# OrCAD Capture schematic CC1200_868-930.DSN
size A3; rev: A; note: CC120XEM_868_915
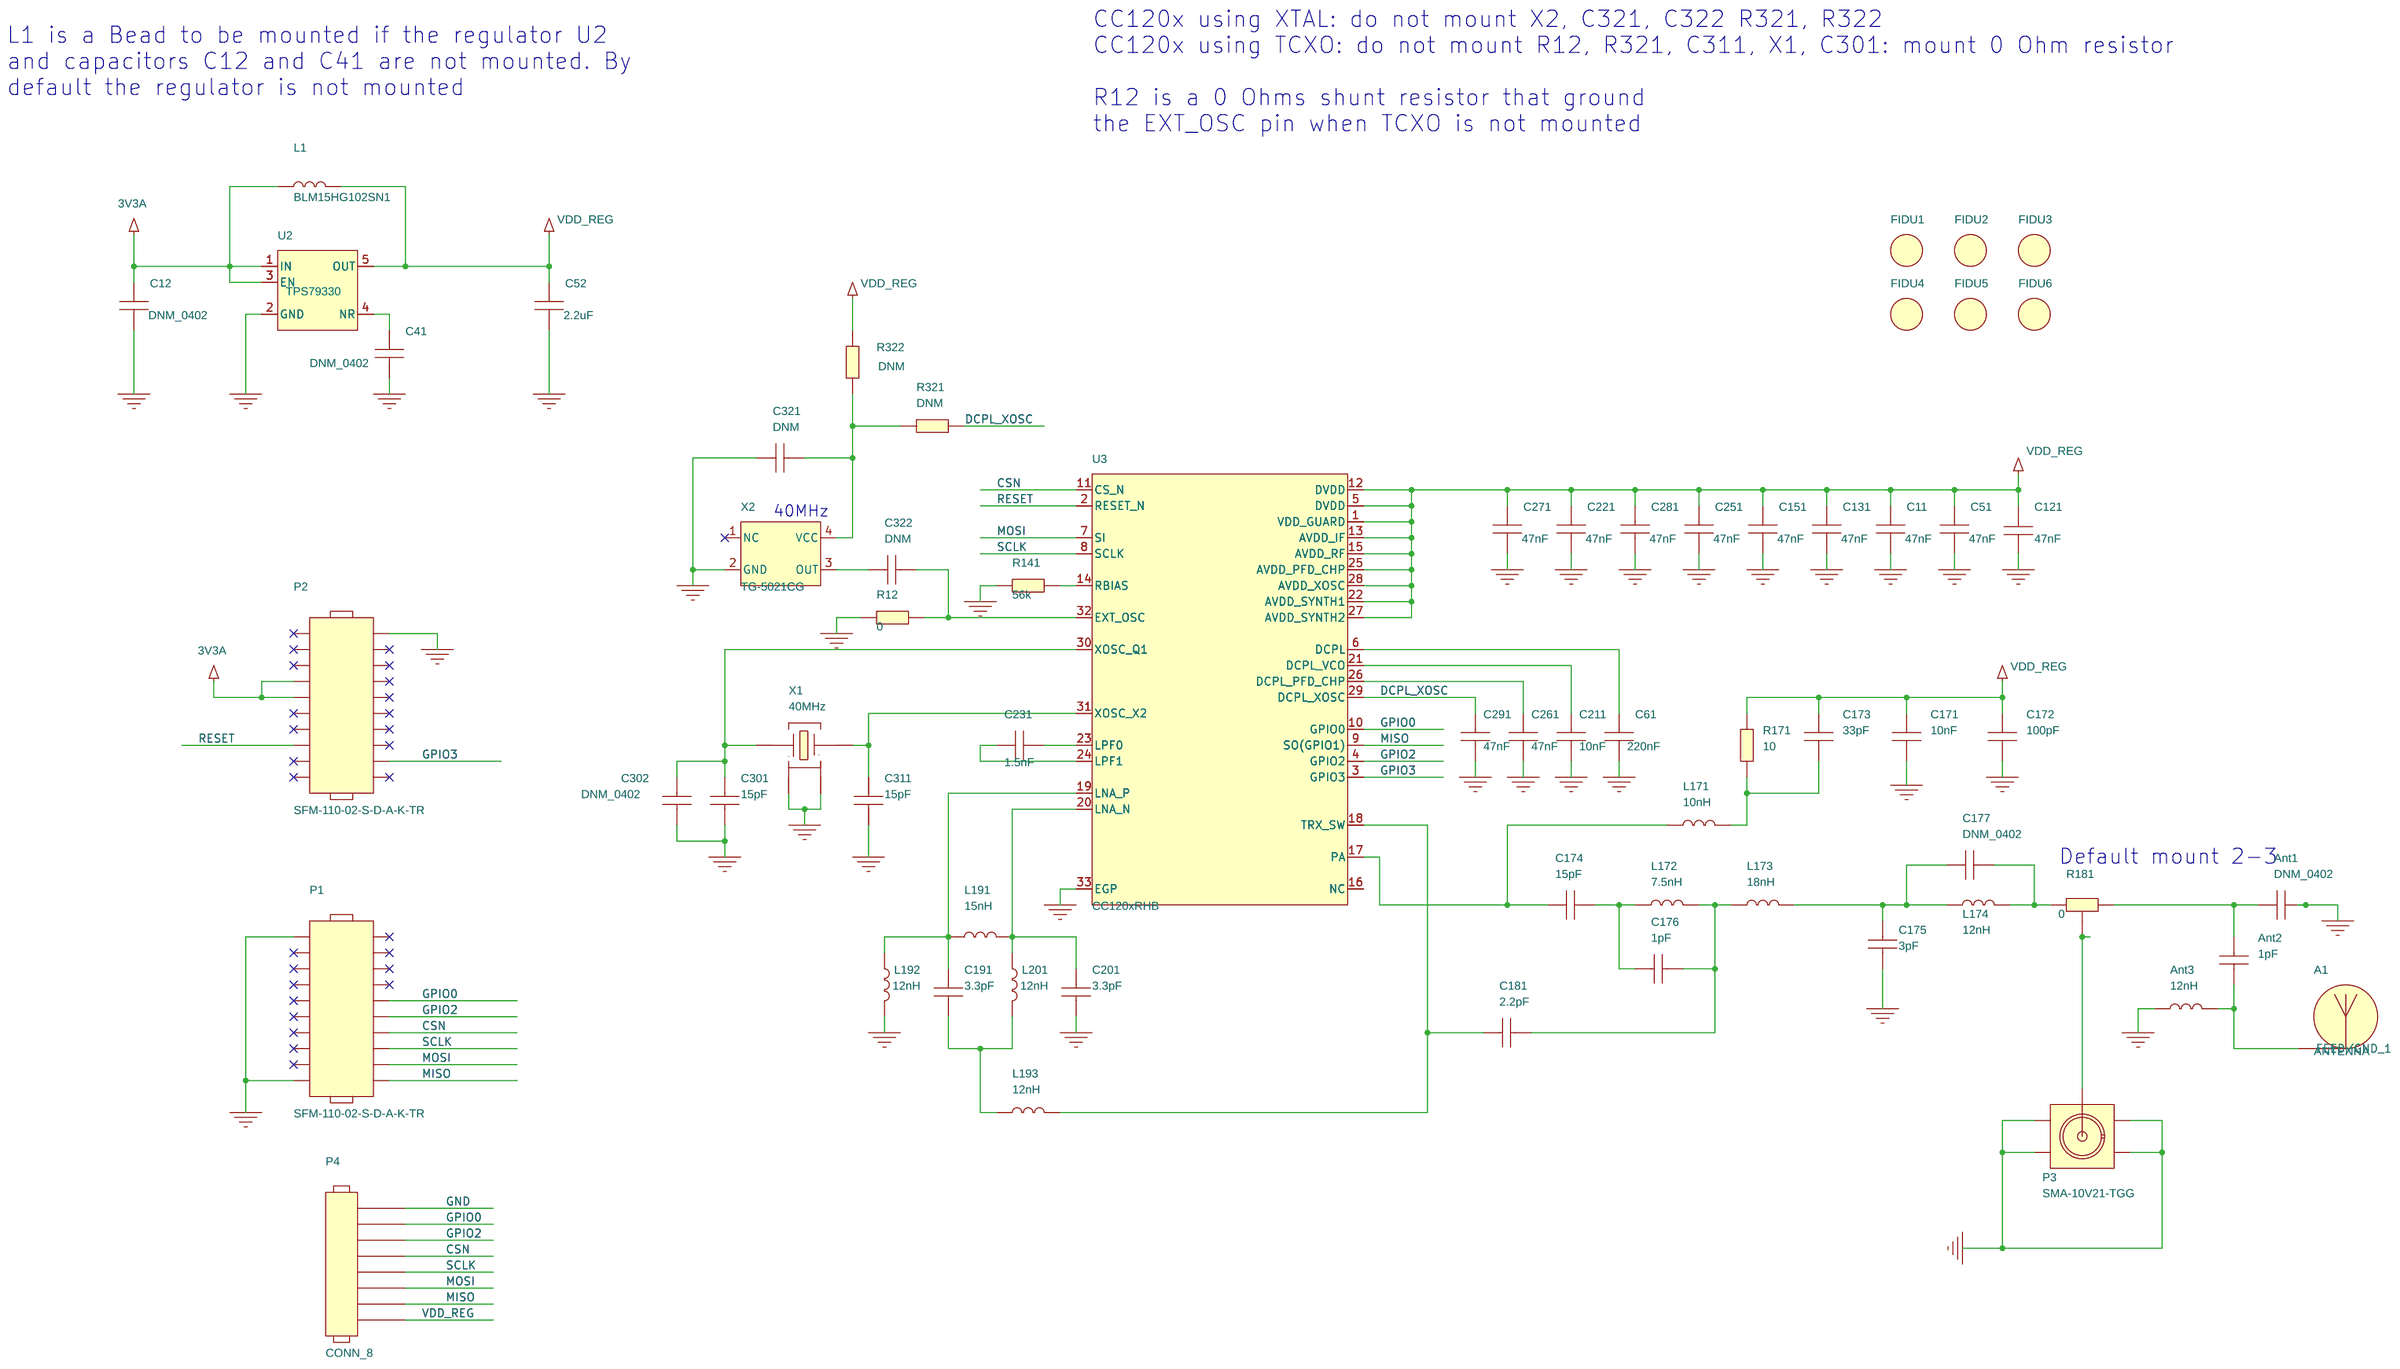
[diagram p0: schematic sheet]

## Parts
A1  ANTENNA  [Antenna868_915MHz]
Ant1  DNM_0402  [CAPC1005X60N]
Ant2  1pF  [CAPC1005X60N]
Ant3  12nH  [IND_0402CSAN]
C11  47nF  [CAPC1005X60N]
C12  DNM_0402  [CAPC1005X60N]
C41  DNM_0402  [CAPC1005X60N]
C51  47nF  [CAPC1005X60N]
C52  2.2uF  [CAPC1608X90N]
C61  220nF  [CAPC1005X60N]
C121  47nF  [CAPC1005X60N]
C131  47nF  [CAPC1005X60N]
C151  47nF  [CAPC1005X60N]
C171  10nF  [CAPC1005X60N]
C172  100pF  [CAPC1005X60N]
C173  33pF  [CAPC1005X60N]
C174  15pF  [CAPC1005X60N]
C175  3pF  [CAPC1005X60N]
C176  1pF  [CAPC1005X60N]
C177  DNM_0402  [CAPC1005X60N]
C181  2.2pF  [CAPC1005X60N]
C191  3.3pF  [CAPC1005X60N]
C201  3.3pF  [CAPC1005X60N]
C211  10nF  [CAPC1005X60N]
C221  47nF  [CAPC1005X60N]
C231  1.5nF  [CAPC1005X60N]
C251  47nF  [CAPC1005X60N]
C261  47nF  [CAPC1005X60N]
C271  47nF  [CAPC1005X60N]
C281  47nF  [CAPC1005X60N]
C291  47nF  [CAPC1005X60N]
C301  15pF  [CAPC1005X60N]
C302  DNM_0402  [CAPC1005X60N]
C311  15pF  [CAPC1005X60N]
C321  DNM  [CAPC1005X60N]
C322  DNM  [CAPC1005X60N]
FIDU1  FIDU_1.27mm  [FID127X142]
FIDU2  FIDU_1.27mm  [FID127X142]
FIDU3  FIDU_1.27mm  [FID127X142]
FIDU4  FIDU_1.27mm  [FID127X142]
FIDU5  FIDU_1.27mm  [FID127X142]
FIDU6  FIDU_1.27mm  [FID127X142]
L1  BLM15HG102SN1  [INDC1005X60N]
L171  10nH  [IND_0402CSAN]
L172  7.5nH  [IND_0402CSAN]
L173  18nH  [INDC1005X60N]
L174  12nH  [IND_0402CSAN]
L191  15nH  [IND_0402CSAN]
L192  12nH  [IND_0402CSAN]
L193  12nH  [IND_0402CSAN]
L201  12nH  [IND_0402CSAN]
P1  SFM-110-02-S-D-A-K-TR  [SAMTEC_SFM11002AN]
P2  SFM-110-02-S-D-A-K-TR  [SAMTEC_SFM11002AN]
P3  SMA-10V21-TGG  [HUSTSAN_SMA10V21TGGAN]
P4  CONN_8  [CON_1x8PAD_t1900cir1100]
R12  0  [RESC1005X40N]
R141  56k  [RESC1005X40N]
R171  10  [RESC1005X40N]
R181  0  [RESC1005X40AN]
R321  DNM  [RESC1005X40N]
R322  DNM  [RESC1005X40N]
U2  TPS79330  [SOT95P280X145-5N]
U3  CC120xRHB  [QFNFC50P500X500X100-33BN]
X1  40MHz  [OSCCC250X320X80-4N]
X2  TG-5021CG  [OSCCC200X250X90-4BN]

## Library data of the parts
A1 = ANTENNA: MECHANIC, ANTENNA PCB HELIX 868/915MHz, SMD; AutoDoc File: http://notefied-dynamic-precision.com/DB/Apps/Desktop/Item/Object.aspx?id=87165; Frequency: 868/915MHz; MPN: Antenna PCB helix 868/915MHz; MPN Status: ACTIVE; Manufacturer: TEXAS INSTRUMENTS; Max Oper Temp: N/A; Min Oper Temp: N/A; Mounting Type: SMD; NOTE Status: PREFERRED; Part Number: 13-00397; Part Type: MECHANIC\ANTENNA; Revision: R001; RoHS Status: ROHS_COMPLIANT
Ant1 C177 = CAPACITOR: CAPACITOR, CERAMIC, N/A VALUE, -55DEGC/+125DEGC, 0402, SMD; ALT_SYMBOLS: CAPC1005X60L,CAPC1005X60M; AutoDoc File: http://notefied-dynamic-precision.com/DB/Apps/Desktop/Item/Object.aspx?id=84862; Budget Currency: USD; Budget Price: 0.00589; MPN: CAPACITOR_0402_DNM_N/A_M; MPN Status: ACTIVE; Manufacturer: Manufacturer selection; Max Oper Temp: +125DEGC; Min Oper Temp: -55DEGC; Mounting Type: SMD; NOTE Status: PREFERRED; PCB Package: 0402; Packing Size: 10000; Packing Type: TAPE_&_REEL; Part Number: 02-04164; Part Type: CAPACITOR\CERAMIC\0402; Revision: R000; RoHS Status: PART NOT KNOWN
Ant2 C176 = CAPACITOR: CAPACITOR, CERAMIC C0G/NP0, 1pF, 50V, -0.1pF/+0.1pF, -55DEGC/+125DEGC, 0402, SMD; ALT_SYMBOLS: CAPC1005X60L,CAPC1005X60M; AutoDoc File: http://notefied-dynamic-precision.com/DB/Apps/Desktop/Item/Object.aspx?id=86074; Budget Currency: USD; Budget Price: 0.008; Datasheet URL 1: http://search.murata.co.jp/Ceramy/image/img/PDF/ENG/GRM1555C1H1R0BA01.pdf; Datasheet URL 2: http://search.murata.co.jp/Ceramy/image/img/PDF/ENG/GRM1555C1H1R0BA01.pdf; Dielectric Type: C0G/NP0; MPN: GRM1555C1H1R0BA01D; MPN Status: ACTIVE; Manufacturer: MURATA; Max Oper Temp: +125DEGC; Max TC: +30PPM/DEGC; Max Tol: +0.1pF; Min Oper Temp: -55DEGC; Min TC: -30PPM/DEGC; Min Tol: -0.1pF; Mounting Type: SMD; NOTE Status: PREFERRED; PCB Package: 0402; Packing Size: 10000; Packing Type: TAPE_&_REEL; Part Number: 02-04367; Part Type: CAPACITOR\CERAMIC\0402; Revision: R001; RoHS Status: ROHS_COMPLIANT; Rtd Voltage: 50V
Ant3 L174 L192 L193 L201 = INDUCTOR: INDUCTOR, CHIP, 12nH, -5%/+5%, 0.5A, -55DEGC/+125DEGC, 0402, SMD; ALT_SYMBOLS: IND_0402CSAM,IND_0402CSAL; AutoDoc File: http://notefied-dynamic-precision.com/DB/Apps/Desktop/Item/Object.aspx?id=86088; Budget Currency: USD; Budget Price: 0.143; Datasheet URL 1: http://search.murata.co.jp/Ceramy/image/img/PDF/ENG/L0075S0080LQW15A_00.pdf; Datasheet URL 2: http://search.murata.co.jp/Ceramy/image/img/PDF/ENG/L0075S0080LQW15A_00.pdf; Frequency: 5.5GHz; MPN: LQW15AN12NJ00D; MPN Status: ACTIVE; Manufacturer: MURATA; Max Oper Temp: +125DEGC; Max Tol: +5%; Min Oper Temp: -55DEGC; Min Tol: -5%; Mounting Type: SMD; NOTE Status: PREFERRED; PCB Package: 0402; Packing Size: 10000; Packing Type: TAPE_&_REEL; Part Number: 03-06556; Part Type: INDUCTOR\CHIP\0402; Resistance: 0.14; Revision: R001; RoHS Status: ROHS_COMPLIANT; Rtd Current: 0.5A; WEIGHT: 0.0008g
C11 C51 C121 C131 C151 C221 C251 C261 C271 C281 C291 = CAPACITOR: CAPACITOR, CERAMIC, X7R, 47nF, 25V, -10%/+10%, -55DEGC/+125DEGC, 0402, SMD; ALT_SYMBOLS: CAPC1005X60L,CAPC1005X60M; AutoDoc File: https://notefied-dynamic-precision.com/NotefiedWebServices/AutoDocs.aspx?itemid=85866; Datasheet URL 1: http://search.murata.co.jp/Ceramy/image/img/PDF/ENG/GRM155R71E473KA88.pdf; Datasheet URL 2: http://search.murata.co.jp/Ceramy/image/img/PDF/ENG/GRM155R71E473KA88.pdf; Dielectric Type: X7R; LifeCycle Status: ACTIVE; MPN: GRM155R71E473KA88D; MPN Status: ACTIVE; Manufacturer: MURATA; Max Oper Temp: +125DEGC; Max Tol: +10%; Min Oper Temp: -55DEGC; Min Tol: -10%; Mounting Type: SMD; NOTE Status: PREFERRED; PCB Package: 0402; Packing Size: 10000; Packing Type: TAPE_&_REEL; Part Number: 02-04324; Part Type: CAPACITOR\CERAMIC\0402; Revision: R001; RoHS Status: ROHS_COMPLIANT; Rtd Voltage: 25V
C12 C41 C302 = CAPACITOR: CAPACITOR, CERAMIC, N/A VALUE, -55DEGC/+125DEGC, 0402, SMD; ALT_SYMBOLS: CAPC1005X60L,CAPC1005X60M; AutoDoc File: https://notefied-dynamic-precision.com/NotefiedWebServices/AutoDocs.aspx?itemid=84862; Budget Currency: USD; Budget Price: 0.00589; MPN: CAPACITOR_0402_DNM_N/A_M; MPN Status: ACTIVE; Manufacturer: Manufacturer selection; Max Oper Temp: +125DEGC; Min Oper Temp: -55DEGC; Mounting Type: SMD; NOTE Status: PREFERRED; PCB Package: 0402; Packing Size: 10000; Packing Type: TAPE_&_REEL; Part Number: 02-04164; Part Type: CAPACITOR\CERAMIC\0402; Revision: R000; RoHS Status: PART NOT KNOWN
C52 = CAPACITOR: CAPACITOR, CERAMIC X5R, 2.2uF, 10V, -10%/+10%, -55DEGC/+85DEGC, 0603, SMD; ALT_SYMBOLS: CAPC1608X90L,CAPC1608X90M; AutoDoc File: https://notefied-dynamic-precision.com/NotefiedWebServices/AutoDocs.aspx?itemid=74514; Budget Currency: EUR; Budget Price: 0.124; Datasheet URL 1: http://search.murata.co.jp/Ceramy/CatalogAction.do?sHinnm=GRM39X5R225K10&sNHinnm=GRM188R61A225KE34&sNhin_key=GRM188R61A225KE34D&sLang=en&sParam=GRM188R61A225KE34D; Datasheet URL 2: http://search.murata.co.jp/Ceramy/CatalogAction.do?sHinnm=GRM39X5R225K10&sNHinnm=GRM188R61A225KE34&sNhin_key=GRM188R61A225KE34D&sLang=en&sParam=GRM188R61A225KE34D; Dielectric Type: X5R; MPN: GRM188R61A225KE34D; MPN Status: ACTIVE; Manufacturer: MURATA; Max Oper Temp: +85DEGC; Max Tol: +10%; Min Oper Temp: -55DEGC; Min Tol: -10%; Mounting Type: SMD; NOTE Status: PREFERRED; PCB Package: 0603; Packing Size: 4000; Packing Type: TAPE_&_REEL; Part Number: 02-02405; Part Type: CAPACITOR\CERAMIC\0603; Revision: R002; RoHS Status: ROHS_COMPLIANT; Rtd Voltage: 10V
C61 = CAPACITOR: CAPACITOR, CERAMIC X5R, 220nF, 10V, -15%/+15%, -55DEGC/+85DEGC, 0402, SMD; ALT_SYMBOLS: CAPC1005X60L,CAPC1005X60M; AutoDoc File: https://notefied-dynamic-precision.com/NotefiedWebServices/AutoDocs.aspx?itemid=86035; Budget Currency: USD; Budget Price: 0.017; Datasheet URL 1: http://search.murata.co.jp/Ceramy/image/img/PDF/ENG/GRM155R61A224KE19.pdf; Datasheet URL 2: http://search.murata.co.jp/Ceramy/image/img/PDF/ENG/GRM155R61A224KE19.pdf; Dielectric Type: X5R; MPN: GRM155R61A224KE19D; MPN Status: ACTIVE; Manufacturer: MURATA; Max Oper Temp: +85DEGC; Max Tol: +15%; Min Oper Temp: -55DEGC; Min Tol: -15%; Mounting Type: SMD; NOTE Status: PREFERRED; PCB Package: 0402; Packing Size: 10000; Packing Type: TAPE_&_REEL; Part Number: 02-04353; Part Type: CAPACITOR\CERAMIC\0402; Revision: R000; RoHS Status: ROHS_COMPLIANT; Rtd Voltage: 10V
C171 C211 = CAPACITOR: CAPACITOR, CERAMIC X7R, 10nF, 25V, -10%/+10%, -55DEGC/+125DEGC, 0402, SMD; ALT_SYMBOLS: CAPC1005X60L,CAPC1005X60M; AutoDoc File: https://notefied-dynamic-precision.com/NotefiedWebServices/AutoDocs.aspx?itemid=73597; Budget Currency: EUR; Budget Price: 0.015; Cage Code: C0151; Datasheet URL 1: http://search.murata.co.jp/Ceramy/image/img/PDF/ENG/GRM155R71E103KA01.pdf; Datasheet URL 2: http://search.murata.co.jp/Ceramy/image/img/PDF/ENG/GRM155R71E103KA01.pdf; Dielectric Type: X7R; MPN: GRM155R71E103KA01D; MPN Status: ACTIVE; Manufacturer: MURATA; Max Oper Temp: +125DEGC; Max Tol: +10%; Min Oper Temp: -55DEGC; Min Tol: -10%; Mounting Type: SMD; NOTE Status: PREFERRED; Old Footprint: CAPC1005X60N,0402; PCB Package: 0402; Packing Size: 10000; Packing Type: TAPE_&_REEL; Part Number: 02-02314; Part Type: CAPACITOR\CERAMIC\0402; Revision: R001; RoHS Status: ROHS_COMPLIANT; Rtd Voltage: 25V
C172 = CAPACITOR: CAPACITOR, CERAMIC C0G/NP0, 100pF, 50V, -5%/+5%, -55DEGC/+125DEGC, 0402, SMD; ALT_SYMBOLS: CAPC1005X60L,CAPC1005X60M; AutoDoc File: https://notefied-dynamic-precision.com/NotefiedWebServices/AutoDocs.aspx?itemid=86072; Budget Currency: USD; Budget Price: 0.004; Datasheet URL 1: http://search.murata.co.jp/Ceramy/image/img/PDF/ENG/GRM1555C1H101JA01.pdf; Datasheet URL 2: http://search.murata.co.jp/Ceramy/image/img/PDF/ENG/GRM1555C1H101JA01.pdf; Dielectric Type: C0G/NP0; MPN: GRM1555C1H101JA01D; MPN Status: ACTIVE; Manufacturer: MURATA; Max Oper Temp: +125DEGC; Max TC: +30PPM/DEGC; Max Tol: +5%; Min Oper Temp: -55DEGC; Min TC: -30PPM/DEGC; Min Tol: -5%; Mounting Type: SMD; NOTE Status: PREFERRED; PCB Package: 0402; Packing Size: 10000; Packing Type: TAPE_&_REEL; Part Number: 02-04365; Part Type: CAPACITOR\CERAMIC\0402; Revision: R000; RoHS Status: ROHS_COMPLIANT; Rtd Voltage: 50V
C173 = CAPACITOR: CAPACITOR, CERAMIC C0G/NP0, 33pF, 50V, -5%/+5%, -55DEGC/+125DEGC, 0402, SMD; ALT_SYMBOLS: CAPC1005X60M,CAPC1005X60L; AutoDoc File: http://notefied-dynamic-precision.com/DB/Apps/Desktop/Item/Object.aspx?id=86036; Budget Currency: USD; Budget Price: 0.004; Datasheet URL 1: http://psearch.murata.com/capacitor/product/GRM1555C1H330JA01%23.pdf; Datasheet URL 2: http://psearch.murata.com/capacitor/product/GRM1555C1H330JA01%23.pdf; Dielectric Type: C0G/NP0; MPN: GRM1555C1H330JA01D; MPN Status: ACTIVE; Manufacturer: MURATA; Max Oper Temp: +125DEGC; Max TC: +30PPM/DEGC; Max Tol: +5%; Min Oper Temp: -55DEGC; Min TC: -30PPM/DEGC; Min Tol: -5%; Mounting Type: SMD; NOTE Status: PREFERRED; PCB Package: 0402; Packing Size: 10000; Packing Type: TAPE_&_REEL; Part Number: 02-04354; Part Type: CAPACITOR\CERAMIC\0402; Revision: R002; RoHS Status: ROHS_COMPLIANT; Rtd Voltage: 50V
C174 = CAPACITOR: CAPACITOR, CERAMIC C0G/NP0, 15pF, 50V, -5%/+5%, -55DEGC/+125DEGC, 0402, SMD; ALT_SYMBOLS: CAPC1005X60L,CAPC1005X60M; AutoDoc File: http://notefied-dynamic-precision.com/DB/Apps/Desktop/Item/Object.aspx?id=86080; Budget Currency: USD; Budget Price: 0.004; Datasheet URL 1: http://search.murata.co.jp/Ceramy/image/img/PDF/ENG/GRM1555C1H150JA01.pdf; Datasheet URL 2: http://search.murata.co.jp/Ceramy/image/img/PDF/ENG/GRM1555C1H150JA01.pdf; Dielectric Type: C0G/NP0; MPN: GRM1555C1H150JA01D; MPN Status: ACTIVE; Manufacturer: MURATA; Max Oper Temp: +125DEGC; Max TC: +30PPM/DEGC; Max Tol: +5%; Min Oper Temp: -55DEGC; Min TC: -30PPM/DEGC; Min Tol: -5%; Mounting Type: SMD; NOTE Status: PREFERRED; PCB Package: 0402; Packing Size: 10000; Packing Type: TAPE_&_REEL; Part Number: 02-04372; Part Type: CAPACITOR\CERAMIC\0402; Revision: R001; RoHS Status: ROHS_COMPLIANT; Rtd Voltage: 50V
C175 = CAPACITOR: CAPACITOR, CERAMIC C0G/NP0, 3pF, 50V, -0.25pF/+0.25pF, -55DEGC/+125DEGC, 0402, SMD; ALT_SYMBOLS: CAPC1005X60L,CAPC1005X60M; AutoDoc File: http://notefied-dynamic-precision.com/DB/Apps/Desktop/Item/Object.aspx?id=87252; Budget Currency: EUR; Budget Price: 0.003; Datasheet URL 1: http://psearch.murata.com/capacitor/product/GRM1555C1H3R0CA01%23.pdf; Datasheet URL 2: http://psearch.murata.com/capacitor/product/GRM1555C1H3R0CA01%23.pdf; Dielectric Type: C0G/NP0; Lead Time: 12; MPN: GRM1555C1H3R0CA01D; MPN Status: ACTIVE; Manufacturer: MURATA; Max Oper Temp: +125DEGC; Max Tol: +0.25pF; Min Oper Temp: -55DEGC; Min Tol: -0.25pF; Mounting Type: SMD; NOTE Status: PREFERRED; PCB Package: 0402; Packing Size: 10000; Packing Type: TAPE_&_REEL; Part Number: 02-04606; Part Type: CAPACITOR\CERAMIC\0402; Revision: R001; RoHS Status: ROHS_COMPLIANT; Rtd Voltage: 50V; WEIGHT: 0.0016g
C181 = CAPACITOR: CAPACITOR, CERAMIC C0G/NP0, 2.2pF, 50V, -0.25pF/+0.25pF, -55DEGC/+125DEGC, 0402, SMD; ALT_SYMBOLS: CAPC1005X60L,CAPC1005X60M; AutoDoc File: http://notefied-dynamic-precision.com/DB/Apps/Desktop/Item/Object.aspx?id=87251; Budget Currency: EUR; Budget Price: 0.003; Datasheet URL 1: http://psearch.murata.com/capacitor/product/GRM1555C1H2R2CA01%23.pdf; Datasheet URL 2: http://psearch.murata.com/capacitor/product/GRM1555C1H2R2CA01%23.pdf; Dielectric Type: C0G/NP0; Lead Time: 12; MPN: GRM1555C1H2R2CA01D; MPN Status: ACTIVE; Manufacturer: MURATA; Max Oper Temp: +125DEGC; Max Tol: +0.25pF; Min Oper Temp: -55DEGC; Min Tol: -0.25pF; Mounting Type: SMD; NOTE Status: PREFERRED; PCB Package: 0402; Packing Size: 10000; Packing Type: TAPE_&_REEL; Part Number: 02-04605; Part Type: CAPACITOR\CERAMIC\0402; Revision: R001; RoHS Status: ROHS_COMPLIANT; Rtd Voltage: 50V; WEIGHT: 0.0016g
C191 C201 = CAPACITOR: CAPACITOR, CERAMIC C0G/NP0, 3.3pF, 50V, -0.25pF/+0.25pF, -55DEGC/+125DEGC, 0402, SMD; ALT_SYMBOLS: CAPC1005X60L,CAPC1005X60M; AutoDoc File: http://notefied-dynamic-precision.com/DB/Apps/Desktop/Item/Object.aspx?id=86077; Budget Currency: USD; Budget Price: 0.004; Datasheet URL 1: http://search.murata.co.jp/Ceramy/image/img/PDF/ENG/GRM1555C1H3R3CA01.pdf; Datasheet URL 2: http://search.murata.co.jp/Ceramy/image/img/PDF/ENG/GRM1555C1H3R3CA01.pdf; Dielectric Type: C0G/NP0; MPN: GRM1555C1H3R3CA01D; MPN Status: ACTIVE; Manufacturer: MURATA; Max Oper Temp: +125DEGC; Max TC: +30PPM/DEGC; Max Tol: +0.25pF; Min Oper Temp: -55DEGC; Min TC: -30PPM/DEGC; Min Tol: -0.25pF; Mounting Type: SMD; NOTE Status: PREFERRED; PCB Package: 0402; Packing Size: 10000; Packing Type: TAPE_&_REEL; Part Number: 02-04369; Part Type: CAPACITOR\CERAMIC\0402; Revision: R001; RoHS Status: ROHS_COMPLIANT; Rtd Voltage: 50V
C231 = CAPACITOR: CAPACITOR, CERAMIC U2J, 1.5nF, 10V, -5%/+5%, -55DEGC/+125DEGC, 0402, SMD; ALT_SYMBOLS: CAPC1005X60L,CAPC1005X60M; AutoDoc File: http://notefied-dynamic-precision.com/DB/Apps/Desktop/Item/Object.aspx?id=87076; Budget Currency: EUR; Budget Price: 0.018; Datasheet URL 1: http://search.murata.co.jp/Ceramy/image/img/A01X/G005/ENG/GRM1557U1A152JA01-01.pdf; Datasheet URL 2: http://search.murata.co.jp/Ceramy/image/img/A01X/G005/ENG/GRM1557U1A152JA01-01.pdf; Dielectric Type: U2J; Lead Time: 10; MPN: GRM1557U1A152JA01D; MPN Status: ACTIVE; Manufacturer: MURATA; Max Oper Temp: +125DEGC; Max TC: +120PPM/DEGC; Max Tol: +5%; Min Oper Temp: -55DEGC; Min TC: -120PPM/DEGC; Min Tol: -5%; Mounting Type: SMD; NOTE Status: PREFERRED; PCB Package: 0402; Packing Size: 10000; Packing Type: TAPE_&_REEL; Part Number: 02-04545; Part Type: CAPACITOR\CERAMIC\0402; Revision: R001; RoHS Status: ROHS_COMPLIANT; Rtd Voltage: 10V
C301 C311 = CAPACITOR: CAPACITOR, CERAMIC C0G/NP0, 15pF, 50V, -5%/+5%, -55DEGC/+125DEGC, 0402, SMD; ALT_SYMBOLS: CAPC1005X60L,CAPC1005X60M; AutoDoc File: https://notefied-dynamic-precision.com/NotefiedWebServices/AutoDocs.aspx?itemid=86080; Budget Currency: USD; Budget Price: 0.004; Datasheet URL 1: http://search.murata.co.jp/Ceramy/image/img/PDF/ENG/GRM1555C1H150JA01.pdf; Datasheet URL 2: http://search.murata.co.jp/Ceramy/image/img/PDF/ENG/GRM1555C1H150JA01.pdf; Dielectric Type: C0G/NP0; MPN: GRM1555C1H150JA01D; MPN Status: ACTIVE; Manufacturer: MURATA; Max Oper Temp: +125DEGC; Max TC: +30PPM/DEGC; Max Tol: +5%; Min Oper Temp: -55DEGC; Min TC: -30PPM/DEGC; Min Tol: -5%; Mounting Type: SMD; NOTE Status: PREFERRED; PCB Package: 0402; Packing Size: 10000; Packing Type: TAPE_&_REEL; Part Number: 02-04372; Part Type: CAPACITOR\CERAMIC\0402; Revision: R000; RoHS Status: ROHS_COMPLIANT; Rtd Voltage: 50V
C321 = CAPACITOR: CAPACITOR, CERAMIC X7R, 100nF, 10V, -10%/+10%, -55DEGC/+125DEGC, 0402, SMD; Budget Currency: EUR; Budget Price: 0.016; Capacitance: 100nF; Datasheet URL 1: http://search.murata.co.jp/Ceramy/image/img/PDF/ENG/GRM155R71A104KA01.pdf; Dielectric Type: X7R; IPC Alternate Footprint: CAPC1005X60L,CAPC1005X60M; KDA Part Number: 50030994-00; KDA Revision: A; KDA Status: RELEASED; KDA net Datasheet URL: http://bkgw-sql-vp01/Documents/Default.aspx?VendorEntryID=8362; KDC Part Number: RJCR4673106/1; Lead Time: 13; LifeCycle Status: GROWTH; MPN: GRM155R71A104KA01D; MPN Status: ACTIVE; Manufacturer: MURATA; Max Oper Temp: +125DEGC; Max Tol: +10%; Min Oper Temp: -55DEGC; Min Tol: -10%; Mounting Type: SMD; NOTE Status: PREFERRED; PCB Package: 0402; Packing Size: 10000; Packing Type: TAPE_&_REEL; Part Number: 02-00760; Part Type: CAPACITOR\CERAMIC\0402; RoHS Status: ROHS_COMPLIANT; Rtd Voltage: 10V
C322 = CAPACITOR: CAPACITOR, CERAMIC C0G/NP0, 22pF, 50V, -5%/+5%, -55DEGC/+125DEGC, 0402, SMD; Budget Currency: USD; Budget Price: 0.004; Capacitance: 22pF; Datasheet URL 1: http://search.murata.co.jp/Ceramy/image/img/PDF/ENG/GRM1555C1H220JA01.pdf; Dielectric Type: C0G/NP0; IPC Alternate Footprint: CAPC1005X60L,CAPC1005X60M; KDA net Datasheet URL: http://bkgw-sql-vp01/Documents/Default.aspx?VendorEntryID=76211; MPN: GRM1555C1H220JA01D; MPN Status: ACTIVE; Manufacturer: MURATA; Max Oper Temp: +125DEGC; Max TC: +30PPM/DEGC; Max Tol: +5%; Min Oper Temp: -55DEGC; Min TC: -30PPM/DEGC; Min Tol: -5%; Mounting Type: SMD; NOTE Status: PREFERRED; PCB Package: 0402; Packing Size: 10000; Packing Type: TAPE_&_REEL; Part Number: 02-04373; Part Type: CAPACITOR\CERAMIC\0402; RoHS Status: ROHS_COMPLIANT; Rtd Voltage: 50V
FIDU1-FIDU6 = FIDMARK: FIDUCIAL MARK, ROUND 1.27MM; Part Number: 19-00300; Part Type: NON_COMPONENT\FIDUCIAL
L1 = INDUCTOR: FILTER, INDUCTOR TYPE, 1000OHM@100MHZ, 25%,250mA, 0402, SMD; Budget Currency: USD; Datasheet URL 1: http://search.murata.co.jp/Ceramy/image/img/PDF/ENG/L0110S0101BLM15H.pdf; IPC Alternate Footprint: INDC1005X60L,INDC1005X60M; KDA net Datasheet URL: http://bkgw-sql-vp01/Documents/Default.aspx?VendorEntryID=10458; Lead Time: 10; LifeCycle Status: ACTIVE; MPN: BLM15HG102SN1D; MPN Status: ACTIVE; Manufacturer: MURATA; Max Oper Temp: +125DEGC; Min Oper Temp: -55DEGC; Min Tol: -25%; Mounting Type: SMD; NOTE Status: PREFERRED; PCB Package: 0402; Part Number: 04-00032; Part Type: FILTER\EMI\0402; RoHS Status: ROHS_COMPLIANT; Rtd Current: 250mA
L171 = INDUCTOR: INDUCTOR, CHIP, 10nH, -5%/+5%, 0.5A, -55DEGC/+125DEGC, 0402, SMD; ALT_SYMBOLS: IND_0402CSAM,IND_0402CSAL; AutoDoc File: http://notefied-dynamic-precision.com/DB/Apps/Desktop/Item/Object.aspx?id=86082; Budget Currency: USD; Budget Price: 0.159; Datasheet URL 1: http://search.murata.co.jp/Ceramy/image/img/PDF/ENG/L0075S0080LQW15A_00.pdf; Datasheet URL 2: http://search.murata.co.jp/Ceramy/image/img/PDF/ENG/L0075S0080LQW15A_00.pdf; Frequency: 5.5GHz; MPN: LQW15AN10NJ00D; MPN Status: ACTIVE; Manufacturer: MURATA; Max Oper Temp: +125DEGC; Max Tol: +5%; Min Oper Temp: -55DEGC; Min Tol: -5%; Mounting Type: SMD; NOTE Status: PREFERRED; PCB Package: 0402; Packing Size: 10000; Packing Type: TAPE_&_REEL; Part Number: 03-06552; Part Type: INDUCTOR\CHIP\0402; Resistance: 0.17; Revision: R001; RoHS Status: ROHS_COMPLIANT; Rtd Current: 0.5A; WEIGHT: 0.0008g
L172 = INDUCTOR: INDUCTOR, CHIP, 7.5nH, -2%/+2%, 0.57A, -55DEGC/+125DEGC, 0402, SMD; ALT_SYMBOLS: IND_0402CSAM,IND_0402CSAL; AutoDoc File: http://notefied-dynamic-precision.com/DB/Apps/Desktop/Item/Object.aspx?id=86081; Budget Currency: USD; Budget Price: 0.13; Datasheet URL 1: http://search.murata.co.jp/Ceramy/image/img/PDF/ENG/L0075S0080LQW15A_00.pdf; Datasheet URL 2: http://search.murata.co.jp/Ceramy/image/img/PDF/ENG/L0075S0080LQW15A_00.pdf; Frequency: 6GHz; MPN: LQW15AN7N5G00D; MPN Status: ACTIVE; Manufacturer: MURATA; Max Oper Temp: +125DEGC; Max Tol: +2%; Min Oper Temp: -55DEGC; Min Tol: -2%; Mounting Type: SMD; NOTE Status: PREFERRED; PCB Package: 0402; Packing Size: 10000; Packing Type: TAPE_&_REEL; Part Number: 03-06551; Part Type: INDUCTOR\CHIP\0402; Resistance: 0.13; Revision: R001; RoHS Status: ROHS_COMPLIANT; Rtd Current: 0.57A; WEIGHT: 0.0008g
L173 = INDUCTOR: INDUCTOR, CHIP, 18nH, -5%/+5%, 0.37A, -55DEGC/+125DEGC, 0402, SMD; ALT_SYMBOLS: INDC1005X60L,INDC1005X60M; AutoDoc File: http://notefied-dynamic-precision.com/DB/Apps/Desktop/Item/Object.aspx?id=87275; Datasheet URL 1: http://search.murata.co.jp/Ceramy/image/img/PDF/ENG/L0075S0080LQW15A_00.pdf; Datasheet URL 2: http://search.murata.co.jp/Ceramy/image/img/PDF/ENG/L0075S0080LQW15A_00.pdf; Frequency: 4.5GHz; MPN: LQW15AN18NJ00D; MPN Status: ACTIVE; Manufacturer: MURATA; Max Oper Temp: +125DEGC; Max Tol: +5%; Min Oper Temp: -55DEGC; Min Tol: -5%; Mounting Type: SMD; NOTE Status: PREFERRED; PCB Package: 0402; Packing Size: 10000; Packing Type: TAPE_&_REEL; Part Number: 03-06593; Part Type: INDUCTOR\CHIP\0402; Resistance: 0.27; Revision: R002; RoHS Status: ROHS_COMPLIANT; Rtd Current: 0.37A
L191 = INDUCTOR: INDUCTOR, CHIP, 15nH, -5%/+5%, 0.46A, -55DEGC/+125DEGC, 0402, SMD; Budget Currency: USD; Budget Price: 0.143; Datasheet URL 1: http://search.murata.co.jp/Ceramy/image/img/PDF/ENG/L0075S0080LQW15A_00.pdf; Frequency: 5GHz; IPC Alternate Footprint: IND_0402CSAM,IND_0402CSAL; KDA net Datasheet URL: http://bkgw-sql-vp01/Documents/Default.aspx?VendorEntryID=76214; MPN: LQW15AN15NJ00D; MPN Status: ACTIVE; Manufacturer: MURATA; Max Oper Temp: +125DEGC; Max Tol: +5%; Min Oper Temp: -55DEGC; Min Tol: -5%; Mounting Type: SMD; NOTE Status: PREFERRED; PCB Package: 0402; Packing Size: 10000; Packing Type: TAPE_&_REEL; Part Number: 03-06555; Part Type: INDUCTOR\CHIP\0402; RoHS Status: ROHS_COMPLIANT; Rtd Current: 0.46A; WEIGHT: 0.0008g
P1 P2 = CONN_HEADER_2X10_P_S: CONNECTOR, HEADER, FEMALE, STRAIGHT, 2 ROWS, 20 PINS, PITCH 1.27mm, SMD; Datasheet URL 1: http://www.samtec.com/ProductInformation/TechnicalSpecifications/CatalogPages.aspx?series=SFM; IPC Alternate Footprint: SAMTEC_SFM11002AL,SAMTEC_SFM11002AM; KDA net Datasheet URL: http://bkgw-sql-vp01/Documents/Default.aspx?VendorEntryID=75090; MPN: SFM-110-02-SM-D-A-K-TR; MPN Status: ACTIVE; Manufacturer: SAMTEC; Max Oper Temp: +125DEGC; Min Oper Temp: -55DEGC; Mounting Type: SMD; NOTE Status: PREFERRED; No Of Pos: 20; No Of Rows: 2; Packing Size: 125; Packing Type: TAPE_&_REEL; Part Number: 06-02251; Part Type: CONNECTOR\HEADER; Pitch: 1.27mm; RoHS Status: ROHS_COMPLIANT
P3 = CONN_COAX_1+4: CONNECTOR, COAX RF, STRAIGHT, FEMALE, 1 PIN, SMD; Datasheet URL 1: http://www.hustsan.com.tw/uploaddir/product/SMA-10V21.pdf; FPLIST: HUSTSAN_SMA10V21TGGAN,HUSTSAN_SMA10V21TGGN; IPC Alternate Footprint: HUSTSAN_SMA10V21TGGL,HUSTSAN_SMA10V21TGGM; KDA net Datasheet URL: http://bkgw-sql-vp01/Documents/Default.aspx?VendorEntryID=75089; MPN Status: ACTIVE; Manufacturer: HUS-TSAN; Mounting Type: SMD; NOTE Status: PREFERRED; No Of Pos: 1; Part Number: 06-02188; Part Type: CONNECTOR\COAX
P4 = CONN_HEADER_0: NON COMPONENT, CONNECTOR, 1 ROW, 8 PINS, PITCH 2.54mm, PTH; AutoDoc File: https://notefied-dynamic-precision.com/NotefiedWebServices/AutoDocs.aspx?itemid=87585; Part Number: 19-00339; Part Type: NON_COMPONENT\CONNECTOR; Revision: R001
R12 = RESISTOR: RESISTOR, JUMPER, -55DEGC/+155DEGC, 0402, SMD; Datasheet URL 1: http://www.koaspeer.com/catimages/Products/RK73Z/RK73Z.pdf; IPC Alternate Footprint: RESC1005X40L,RESC1005X40M; KDA net Datasheet URL: http://bkgw-sql-vp01/Documents/Default.aspx?VendorEntryID=2714; KDC Part Number: REPR6342620/0; Lead Time: 14; LifeCycle Status: ACTIVE; MPN: RK73Z1ETTP; MPN Status: ACTIVE; Manufacturer: KOA SPEER; Max Oper Temp: +155DEGC; Min Oper Temp: -55DEGC; Mounting Type: SMD; NOTE Status: PREFERRED; PCB Package: 0402; Part Number: 01-01784; Part Type: RESISTOR\JUMPER\0402; RoHS Status: ROHS_COMPLIANT; Rtd Current: 1A
R141 = RESISTOR: RESISTOR, THICK FILM, 56k, -1%/+1%, 0.063W, 50V, -55DEGC/+155DEGC, 0402, SMD; Datasheet URL 1: http://www.koaspeer.com/catimages/Products/RK73H/RK73H.pdf; IPC Alternate Footprint: RESC1005X40L,RESC1005X40M; KDA net Datasheet URL: http://bkgw-sql-vp01/Documents/Default.aspx?VendorEntryID=75547; MPN: RK73H1ETTP5602F; MPN Status: ACTIVE; Manufacturer: KOA SPEER; Max Oper Temp: +155DEGC; Max TC: +100PPM/DEGC; Max Tol: +1%; Min Oper Temp: -55DEGC; Min TC: -100PPM/DEGC; Min Tol: -1%; Mounting Type: SMD; NOTE Status: PREFERRED; PCB Package: 0402; Part Number: 01-16848; Part Type: RESISTOR\0402\PRECISION; Resistor Type: THICK FILM; RoHS Status: ROHS_COMPLIANT; Rtd Power: 0.063W; Rtd Voltage: 50V
R171 = RESISTOR: RESISTOR, THICK FILM, 10, -5%/+5%, 0.063W, 50V, -55DEGC/+155DEGC, 0402, SMD; ALT_SYMBOLS: RESC1005X40L,RESC1005X40M; AutoDoc File: http://notefied-dynamic-precision.com/DB/Apps/Desktop/Item/Object.aspx?id=75667; Budget Currency: USD; Budget Price: 0.00244; LifeCycle Status: ACTIVE; MPN: RESISTOR_0402_10_+/-5%_50V_0.063W_M_+/-200PPM; MPN Status: ACTIVE; Manufacturer: Manufacturer selection; Max Oper Temp: +155DEGC; Max TC: +200PPM/DEGC; Max Tol: +5%; Min Oper Temp: -55DEGC; Min TC: -200PPM/DEGC; Min Tol: -5%; Mounting Type: SMD; NOTE Status: PREFERRED; PCB Package: 0402; Packing Size: 10000; Packing Type: TAPE_&_REEL; Part Number: 01-11612; Part Type: RESISTOR\0402; Resistor Type: THICK FILM; Revision: R000; RoHS Status: ROHS_COMPLIANT; Rtd Power: 0.063W; Rtd Voltage: 50V
R181 = RESISTOR_3PORTS: RESISTOR, JUMPER, 3 PORTS, -55DEGC/+155DEGC, 0402, SMD; ALT_SYMBOLS: RESC1005X40AL,RESC1005X40AM,RESC1005X40BL,RESC1005X40BM; AutoDoc File: http://notefied-dynamic-precision.com/DB/Apps/Desktop/Item/Object.aspx?id=84964; Datasheet URL 1: http://www.koaspeer.com/catimages/Products/RK73Z/RK73Z.pdf; Datasheet URL 2: http://www.koaspeer.com/catimages/Products/RK73Z/RK73Z.pdf; FPLIST: RESC1005X40AN,RESC1005X40BN; Lead Time: 14; LifeCycle Status: ACTIVE; MPN: RK73Z1ETTP; MPN Status: ACTIVE; Manufacturer: KOA SPEER; Max Oper Temp: +155DEGC; Min Oper Temp: -55DEGC; Mounting Type: SMD; NOTE Status: PREFERRED; Old Footprint: RESC1005X40AN,RESC1005X40BN; PCB Package: 0402; Part Number: 01-16574; Part Type: RESISTOR\0402; Resistor Type: THICK FILM; Revision: R001; RoHS Status: ROHS_COMPLIANT
R321 R322 = RESISTOR: RESISTOR, DO NOT MOUNT, 0402, SMD; IPC Alternate Footprint: RESC1005X40L,RESC1005X40M; KDA net Datasheet URL: http://bkgw-sql-vp01/Documents/Default.aspx?VendorEntryID=69895; MPN Status: ACTIVE; Manufacturer: DO NOT MOUNT; Mounting Type: SMD; NOTE Status: PREFERRED; PCB Package: 0402; Part Number: 01-02472; Part Type: RESISTOR\0402; RoHS Status: PART NOT KNOWN
U2 = IC_PM_TPS79930_SOT5_0: IC, ANALOG, HIGH PSRR FAST RF LOW DROPOUT REGULATOR IN WAFER CHIP SCALE, VIN:2.7V TO 5.5V, VOUT: 3V, SOT23-5, SMD; Budget Currency: USD; Budget Price: 0.23; IPC Alternate Footprint: SOT95P280X145-5L,SOT95P280X145-5M; KDA net Datasheet URL: http://bkgw-sql-vp01/Documents/Default.aspx?VendorEntryID=5116; Lead Time: 20; LifeCycle Status: MATURITY; MPN: TPS79330DBVR; MPN Status: ACTIVE; MSL: 1; MTBF: 2.37*10^9; Manufacturer: TEXAS INSTRUMENTS; Max Oper Temp: +85DEGC; Min Oper Temp: -40DEGC; Mounting Type: SMD; NOTE Status: NOT_PREFERRED; PCB Package: SOT23-5; Packing Size: 3000; Packing Type: TAPE_&_REEL; Part Number: 18-01358; Part Type: IC\ANALOG\PM\LINEAR; RoHS Status: ROHS_COMPLIANT; Rtd Current: 0.2A; Rtd Voltage: 3V; WEIGHT: 0.0203g
U3 = IC_RF_CC1120_QFN32: IC, ANALOG RF, CC120xRHB, N/A, QFN32, SMD; ALT_SYMBOLS: QFNFC50P500X500X100-33BL,QFNFC50P500X500X100-33BM; AutoDoc File: http://notefied-dynamic-precision.com/DB/Apps/Desktop/Item/Object.aspx?id=87160; Datasheet URL 1: www.ti.com; Datasheet URL 2: www.ti.com; MPN Status: ACTIVE; Manufacturer: TEXAS INSTRUMENTS; Max Oper Temp: N/A; Min Oper Temp: N/A; Mounting Type: SMD; NOTE Status: PREFERRED; PCB Package: QFN32; Part Number: 18-28112; Part Type: IC\ANALOG\RF\TRANSCEIVER; Revision: R001; RoHS Status: ROHS_COMPLIANT; Rtd Voltage: N/A
X1 = XTAL_4PIN_S: CRYSTAL, OSCILATOR, 40MHz, -15PPM/DEGC/+15PPM/DEGC, 100V, -20DEGC/+75DEGC, SMD; ALT_SYMBOLS: OSCCC250X320X80-4L,OSCCC250X320X80-4M; AutoDoc File: http://notefied-dynamic-precision.com/DB/Apps/Desktop/Item/Object.aspx?id=87072; Capacitance: 10pF; Datasheet URL 1: http://www.ndk.com/images/products/catalog/c_NX3225SA-STD-CSQ-1_e.pdf; Datasheet URL 2: http://www.ndk.com/images/products/catalog/c_NX3225SA-STD-CSQ-1_e.pdf; MPN: NX3225SA 40MHz EXS00A-CS03880; MPN Status: ACTIVE; Manufacturer: NIHON DEMPA KOGYO CO., LTD; Max Oper Temp: +75DEGC; Max TC: +15PPM/DEGC; Max Tol: +10PPM; Min Oper Temp: -20DEGC; Min TC: -15PPM/DEGC; Min Tol: -10PPM; Mounting Type: SMD; NOTE Status: PREFERRED; Part Number: 12-00469; Part Type: CRYSTAL\OSCILLATOR; Revision: R001; RoHS Status: ROHS_COMPLIANT; Rtd Voltage: 100V
X2 = XTAL_TG-5021CG: CRYSTAL, OSCILATOR, TBD, 2.3V TO 3.6V, -30DEGC/+85DEGC, , SMD; Capacitance: 10pF; Datasheet URL 1: http://ndap3-net.ebz.epson.co.jp/w/www/PDFS/epdoc_qd.nsf/8ad692132af59f4c4925706f002d4d3a/ade1325b0efff3c24925757b0022a5c6/$FILE/TG-5021CG_E114.pdf; Frequency: TBD; IPC Alternate Footprint: OSCCC200X250X90-4BL,OSCCC200X250X90-4BM; KDA net Datasheet URL: http://bkgw-sql-vp01/Documents/Default.aspx?VendorEntryID=76227; MPN: TG_5021CG; MPN Status: ACTIVE; Manufacturer: Epson Toyocom; Max Oper Temp: +85DEGC; Min Oper Temp: -30DEGC; Mounting Type: SMD; NOTE Status: PREFERRED; Part Number: 12-00451; Part Type: CRYSTAL\OSCILLATOR; RoHS Status: ROHS_COMPLIANT; Rtd Voltage: 2.3V TO 3.6V

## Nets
3V3A: C12.1 L1.1 P2.7 P2.9 U2.1(IN) U2.3(EN)
GND: Ant1.2 Ant3.1 C11.2 C12.2 C41.2 C51.2 C52.2 C61.2 C121.1 C131.2 C151.2 C171.2 C172.2 C175.2 C201.2 C211.2 C221.2 C251.2 C261.2 C271.2 C281.2 C291.2 C301.2 C302.2 C311.2 C321.1 L192.2 P1.1 P1.19 P2.2 P3.2 P3.3 P3.4 P3.5 P4.1 R12.2 R141.2 U2.2(GND) U3.33(EGP) X1.2 X1.4 X2.2(GND)
VDD_REG: C11.1 C51.1 C52.1 C121.2 C131.1 C151.1 C171.1 C172.1 C173.1 C221.1 C251.1 C271.1 C281.1 L1.2 P4.8 R171.2 R322.1 U2.5(OUT) U3.1(VDD_GUARD) U3.5(DVDD) U3.12(DVDD) U3.13(AVDD_IF) U3.15(AVDD_RF) U3.22(AVDD_SYNTH1) U3.25(AVDD_PFD_CHP) U3.27(AVDD_SYNTH2) U3.28(AVDD_XOSC)
CSN: P1.14 P4.4 U3.11(CS_N)
DCPL_XOSC: C291.1 R321.1 U3.29(DCPL_XOSC)
GPIO0: P1.10 P4.2 U3.10(GPIO0)
GPIO2: P1.12 P4.3 U3.4(GPIO2)
GPIO3: P2.18 U3.3(GPIO3)
MISO: P1.20 P4.7 U3.9(SO(GPIO1))
MOSI: P1.18 P4.6 U3.7(SI)
RESET: P2.15 U3.2(RESET_N)
SCLK: P1.16 P4.5 U3.8(SCLK)
N02751: C41.1 U2.4(NR)
N03028: C61.1 U3.6(DCPL)
N03080: C211.1 U3.21(DCPL_VCO)
N03171: C261.1 U3.26(DCPL_PFD_CHP)
N03297: C231.2 U3.23(LPF0)
N03301: C231.1 U3.24(LPF1)
N03775: C301.1 C302.1 U3.30(XOSC_Q1) X1.1
N03827: C311.1 U3.31(XOSC_X2) X1.3
N03987: C322.1 X2.3(OUT)
N04005: C322.2 R12.1 U3.32(EXT_OSC)
N04250: C321.2 R321.2 R322.2 X2.4(VCC)
N04524: R141.1 U3.14(RBIAS)
N06943: C191.1 L191.1 L192.1 U3.19(LNA_P)
N06950: C201.1 L191.2 L201.1 U3.20(LNA_N)
N06973: C191.2 L193.1 L201.2
N07362: C181.1 L193.2 U3.18(TRX_SW)
N07471: C174.1 L171.1 U3.17(PA)
N07475: C174.2 C176.1 L172.1
N07485: C176.2 C181.2 L172.2 L173.1
N07738: C175.1 C177.1 L173.2 L174.1
N07781: C177.2 L174.2 R181.2
N08395: C173.2 L171.2 R171.1
N35337: Ant1.1 Ant2.1 R181.1
N35679: A1.1(FEED/GND) Ant2.2 Ant3.2
N41911: P3.1 R181.3

Not connected (* = marked no-connect by the designer): FIDU1 1; FIDU2 1; FIDU3 1; FIDU4 1; FIDU5 1; FIDU6 1; P1 2* 3* 4* 5* 6* 7* 8* 9* 11* 13* 15* 17*; P2 1* 3* 4* 5* 6* 8* 10* 11* 12* 13* 14* 16* 17* 19* 20*; U3 16(NC); X2 1(NC)*

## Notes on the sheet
- L1 is a Bead to be mounted if the regulator U2
  and capacitors C12 and C41 are not mounted. By
  default the regulator is not mounted
- CC120x using XTAL: do not mount X2, C321, C322 R321, R322
  CC120x using TCXO: do not mount R12, R321, C311, X1, C301: mount 0 Ohm resistor
  R12 is a 0 Ohms shunt resistor that ground
  the EXT_OSC pin when TCXO is not mounted
- 40MHz
- Default mount 2-3
